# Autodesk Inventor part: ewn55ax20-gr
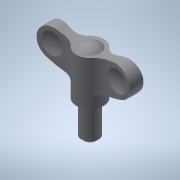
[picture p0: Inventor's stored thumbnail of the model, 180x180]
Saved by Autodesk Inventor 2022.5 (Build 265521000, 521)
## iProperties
Created: 2016-12
Part Number: ewn55ax20-gr
Material: 一般
Document SubType Name: Modeling
Designer: imaocorp
Density: 1 g/cm^3
Appearance: 既定
Author: imaocorp
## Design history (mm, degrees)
node "ewn55ax20-gr.x_t1"
node "ewn55ax20-gr"
node "Base1"
